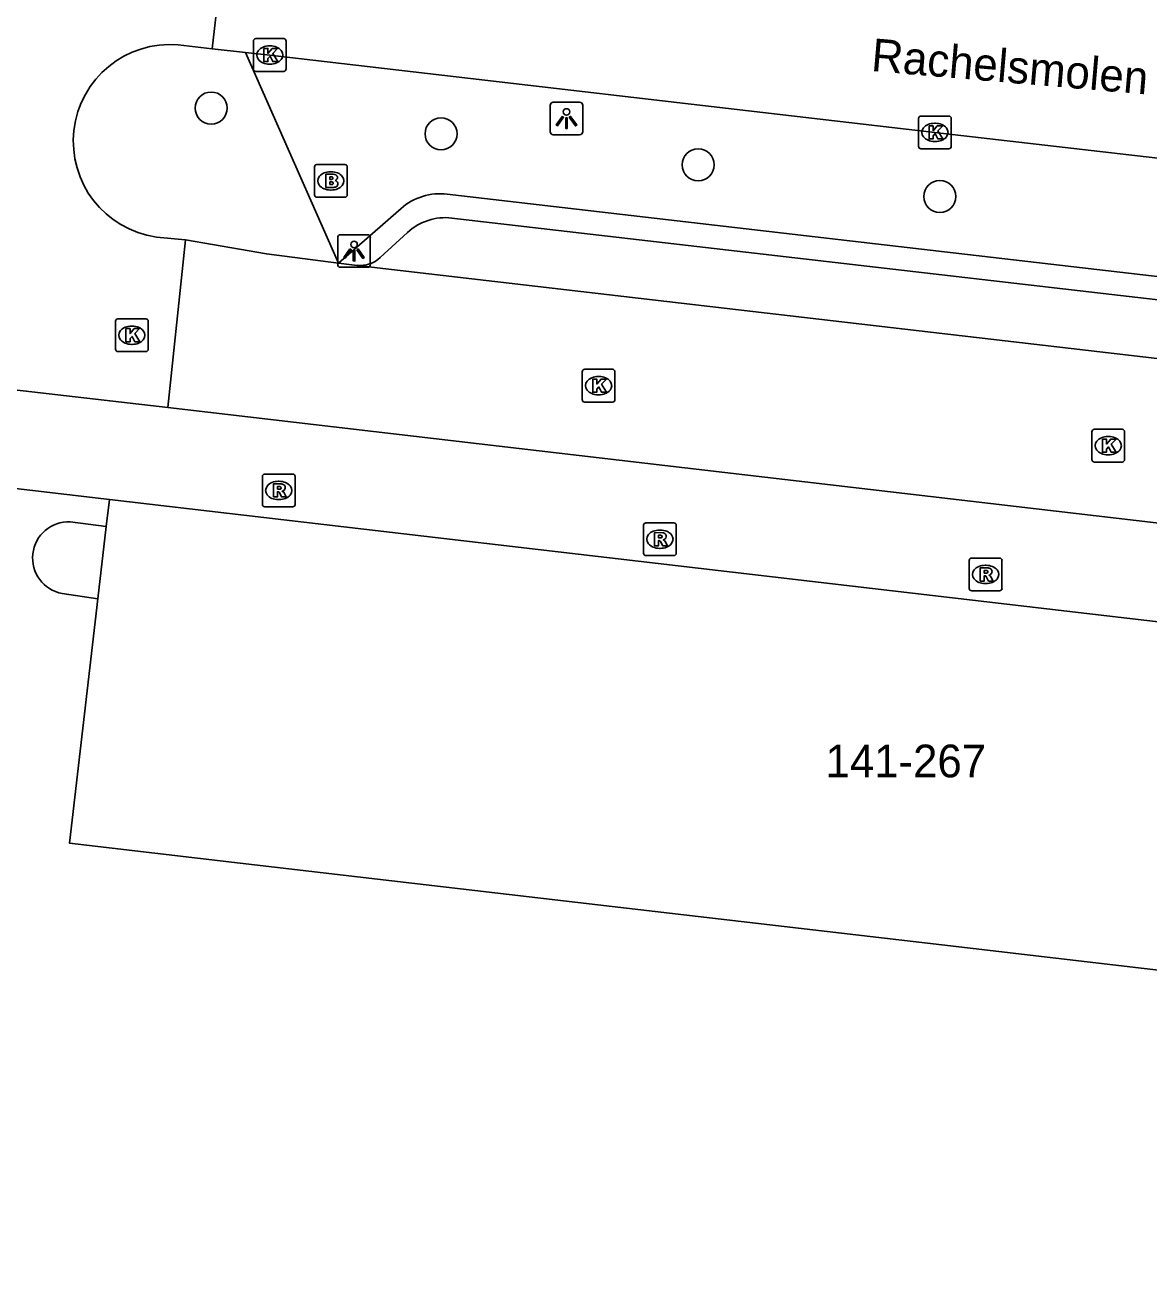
# Model space of a CAD drawing. Extents: x 161243 to 161752, y 384138 to 384885.
# Drawn here: x 161530.14 to 161564.47, y 384599.27 to 384637.78 of the extents above; entities that cross this region are included whole.
import ezdxf

# ---------------------------------------------------------------- set-up
doc = ezdxf.new("R2010")
doc.units = 0
for name, color, linetype in [('IMGEO_Berm_groen', 7, 'Continuous'), ('IMGEO_Boom', 7, 'Continuous'), ('IMGEO_Brandkraan', 7, 'Continuous'), ('IMGEO_Kolk', 7, 'Continuous'), ('IMGEO_Lichtpunt', 7, 'Continuous'), ('IMGEO_Openbare_ruimte_label', 7, 'Continuous'), ('IMGEO_Pand', 7, 'Continuous'), ('IMGEO_Pand_nummerreeks', 7, 'Continuous'), ('IMGEO_Rijbaan_lokaal_open', 7, 'Continuous'), ('IMGEO_Rioolput', 7, 'Continuous'), ('IMGEO_Voetpad_open', 7, 'Continuous')]:
    doc.layers.add(name, color=color, linetype=linetype)

msp = doc.modelspace()

# ---------------------------------------------------------------- linework, layer by layer
at = {"layer": 'IMGEO_Berm_groen'}
msp.add_lwpolyline([(161539.715, 384630.511), (161536.877, 384636.946)], dxfattribs=at)
at = {"layer": 'IMGEO_Boom'}
for centre in [(161535.824, 384635.246), (161542.847, 384634.458), (161550.703, 384633.512), (161558.087, 384632.544)]:
    msp.add_circle(centre, 0.489, dxfattribs=at)
at = {"layer": 'IMGEO_Brandkraan'}
for p, q in [((161538.979, 384632.596), (161538.979, 384633.448)), ((161539.054, 384633.522), (161539.906, 384633.522)), ((161539.467, 384633.302), (161539.492, 384633.302)), ((161539.98, 384633.448), (161539.98, 384632.596)), ((161539.906, 384632.522), (161539.054, 384632.522)), ((161539.49, 384632.742), (161539.465, 384632.742))]:
    msp.add_line(p, q, dxfattribs=at)
for points in [[(161538.979, 384632.596), (161538.979, 384633.448)], [(161539.054, 384633.522), (161539.906, 384633.522)], [(161539.98, 384633.448), (161539.98, 384632.596)], [(161539.327, 384633.222), (161539.327, 384632.822), (161539.54, 384632.822)], [(161539.558, 384633.222), (161539.327, 384633.222)], [(161539.506, 384633.141), (161539.452, 384633.141), (161539.452, 384633.065)], [(161539.452, 384633.065), (161539.505, 384633.065)], [(161539.514, 384632.989), (161539.452, 384632.989), (161539.452, 384632.908)], [(161539.452, 384632.908), (161539.514, 384632.908)], [(161539.906, 384632.522), (161539.054, 384632.522)]]:
    msp.add_lwpolyline(points, dxfattribs=at)
for centre, radius, start, end in [((161539.056, 384633.446), 0.0765, 91.552, 178.448), ((161539.056, 384633.446), 0.0765, 91.552, 178.448), ((161539.904, 384633.446), 0.0765, 1.552, 88.448), ((161539.904, 384633.446), 0.0765, 1.552, 88.448), ((161539.507, 384633.103), 0.0379, 267.8285, 90.9355), ((161539.515, 384632.948), 0.0404, 269.8759, 90.5077), ((161539.546, 384633.073), 0.251, 268.6676, 293.5347), ((161539.562, 384633.077), 0.145, 59.4692, 91.5367), ((161539.587, 384633.124), 0.0922, 285.5137, 58.1501), ((161539.592, 384632.932), 0.105, 301.3115, 78.989), ((161539.056, 384632.598), 0.0765, 181.552, 268.448), ((161539.056, 384632.598), 0.0765, 181.552, 268.448), ((161539.904, 384632.598), 0.0765, 271.552, 358.448), ((161539.904, 384632.598), 0.0765, 271.552, 358.448)]:
    msp.add_arc(centre, radius, start, end, dxfattribs=at)
for centre, major_axis, ratio, start_param, end_param in [((161539.466, 384633.022), (-0.387, 0.002), 0.722429, 4.712389, 7.853982), ((161539.491, 384633.022), (-0.39, 0.002), 0.717154, 1.570796, 4.712389)]:
    msp.add_ellipse(centre, major_axis=major_axis, ratio=ratio, start_param=start_param, end_param=end_param, dxfattribs=at)
at = {"layer": 'IMGEO_Kolk'}
for p, q in [((161537.114, 384636.441), (161537.114, 384637.293)), ((161537.189, 384637.367), (161538.041, 384637.367)), ((161537.602, 384637.147), (161537.627, 384637.147)), ((161538.115, 384637.293), (161538.115, 384636.441)), ((161538.041, 384636.367), (161537.189, 384636.367)), ((161537.625, 384636.587), (161537.6, 384636.587)), ((161557.438, 384634.076), (161557.438, 384634.928)), ((161557.513, 384635.002), (161558.365, 384635.002)), ((161557.926, 384634.782), (161557.951, 384634.782)), ((161558.439, 384634.928), (161558.439, 384634.076)), ((161558.365, 384634.002), (161557.513, 384634.002)), ((161557.949, 384634.222), (161557.924, 384634.222)), ((161532.899, 384627.882), (161532.899, 384628.734)), ((161532.974, 384628.808), (161533.826, 384628.808)), ((161533.9, 384628.734), (161533.9, 384627.882)), ((161533.387, 384628.588), (161533.412, 384628.588)), ((161533.41, 384628.028), (161533.385, 384628.028)), ((161533.826, 384627.808), (161532.974, 384627.808)), ((161547.161, 384626.34), (161547.161, 384627.192)), ((161547.236, 384627.266), (161548.088, 384627.266)), ((161548.162, 384627.192), (161548.162, 384626.34)), ((161547.649, 384627.046), (161547.674, 384627.046)), ((161547.672, 384626.486), (161547.647, 384626.486)), ((161548.088, 384626.266), (161547.236, 384626.266)), ((161562.735, 384624.508), (161562.735, 384625.36)), ((161562.81, 384625.434), (161563.662, 384625.434)), ((161563.223, 384625.214), (161563.248, 384625.214)), ((161563.736, 384625.36), (161563.736, 384624.508)), ((161563.662, 384624.434), (161562.81, 384624.434)), ((161563.246, 384624.654), (161563.221, 384624.654))]:
    msp.add_line(p, q, dxfattribs=at)
for points in [[(161537.114, 384636.441), (161537.114, 384637.293)], [(161537.189, 384637.367), (161538.041, 384637.367)], [(161538.115, 384637.293), (161538.115, 384636.441)], [(161537.435, 384637.067), (161537.558, 384637.067), (161537.558, 384636.916), (161537.688, 384637.067), (161537.852, 384637.067), (161537.706, 384636.916), (161537.859, 384636.667), (161537.707, 384636.667), (161537.622, 384636.831), (161537.558, 384636.764), (161537.558, 384636.667), (161537.435, 384636.667), (161537.435, 384637.067)], [(161538.041, 384636.367), (161537.189, 384636.367)], [(161557.438, 384634.076), (161557.438, 384634.928)], [(161557.513, 384635.002), (161558.365, 384635.002)], [(161558.439, 384634.928), (161558.439, 384634.076)], [(161557.759, 384634.702), (161557.882, 384634.702), (161557.882, 384634.551), (161558.012, 384634.702), (161558.176, 384634.702), (161558.03, 384634.551), (161558.183, 384634.302), (161558.031, 384634.302), (161557.946, 384634.466), (161557.882, 384634.399), (161557.882, 384634.302), (161557.759, 384634.302), (161557.759, 384634.702)], [(161558.365, 384634.002), (161557.513, 384634.002)], [(161532.899, 384627.882), (161532.899, 384628.734)], [(161532.974, 384628.808), (161533.826, 384628.808)], [(161533.9, 384628.734), (161533.9, 384627.882)], [(161533.22, 384628.508), (161533.343, 384628.508), (161533.343, 384628.357), (161533.473, 384628.508), (161533.637, 384628.508), (161533.491, 384628.357), (161533.644, 384628.108), (161533.492, 384628.108), (161533.407, 384628.272), (161533.343, 384628.205), (161533.343, 384628.108), (161533.22, 384628.108), (161533.22, 384628.508)], [(161533.826, 384627.808), (161532.974, 384627.808)], [(161547.161, 384626.34), (161547.161, 384627.192)], [(161547.236, 384627.266), (161548.088, 384627.266)], [(161548.162, 384627.192), (161548.162, 384626.34)], [(161547.482, 384626.966), (161547.605, 384626.966), (161547.605, 384626.815), (161547.735, 384626.966), (161547.899, 384626.966), (161547.753, 384626.815), (161547.906, 384626.566), (161547.754, 384626.566), (161547.669, 384626.73), (161547.605, 384626.663), (161547.605, 384626.566), (161547.482, 384626.566), (161547.482, 384626.966)], [(161548.088, 384626.266), (161547.236, 384626.266)], [(161562.735, 384624.508), (161562.735, 384625.36)], [(161562.81, 384625.434), (161563.662, 384625.434)], [(161563.736, 384625.36), (161563.736, 384624.508)], [(161563.056, 384625.134), (161563.179, 384625.134), (161563.179, 384624.983), (161563.309, 384625.134), (161563.473, 384625.134), (161563.327, 384624.983), (161563.48, 384624.734), (161563.328, 384624.734), (161563.243, 384624.898), (161563.179, 384624.831), (161563.179, 384624.734), (161563.056, 384624.734), (161563.056, 384625.134)], [(161563.662, 384624.434), (161562.81, 384624.434)]]:
    msp.add_lwpolyline(points, dxfattribs=at)
for centre, start, end in [((161537.191, 384637.291), 91.552, 178.448), ((161537.191, 384637.291), 91.552, 178.448), ((161538.039, 384637.291), 1.552, 88.448), ((161538.039, 384637.291), 1.552, 88.448), ((161537.191, 384636.443), 181.552, 268.448), ((161537.191, 384636.443), 181.552, 268.448), ((161538.039, 384636.443), 271.552, 358.448), ((161538.039, 384636.443), 271.552, 358.448), ((161557.515, 384634.926), 91.552, 178.448), ((161557.515, 384634.926), 91.552, 178.448), ((161558.363, 384634.926), 1.552, 88.448), ((161558.363, 384634.926), 1.552, 88.448), ((161557.515, 384634.078), 181.552, 268.448), ((161557.515, 384634.078), 181.552, 268.448), ((161558.363, 384634.078), 271.552, 358.448), ((161558.363, 384634.078), 271.552, 358.448), ((161532.976, 384628.732), 91.552, 178.448), ((161532.976, 384628.732), 91.552, 178.448), ((161533.824, 384628.732), 1.552, 88.448), ((161533.824, 384628.732), 1.552, 88.448), ((161532.976, 384627.884), 181.552, 268.448), ((161532.976, 384627.884), 181.552, 268.448), ((161533.824, 384627.884), 271.552, 358.448), ((161533.824, 384627.884), 271.552, 358.448), ((161547.238, 384627.19), 91.552, 178.448), ((161547.238, 384627.19), 91.552, 178.448), ((161548.086, 384627.19), 1.552, 88.448), ((161548.086, 384627.19), 1.552, 88.448), ((161547.238, 384626.342), 181.552, 268.448), ((161547.238, 384626.342), 181.552, 268.448), ((161548.086, 384626.342), 271.552, 358.448), ((161548.086, 384626.342), 271.552, 358.448), ((161562.812, 384625.358), 91.552, 178.448), ((161562.812, 384625.358), 91.552, 178.448), ((161563.66, 384625.358), 1.552, 88.448), ((161563.66, 384625.358), 1.552, 88.448), ((161562.812, 384624.51), 181.552, 268.448), ((161562.812, 384624.51), 181.552, 268.448), ((161563.66, 384624.51), 271.552, 358.448), ((161563.66, 384624.51), 271.552, 358.448)]:
    msp.add_arc(centre, 0.0765, start, end, dxfattribs=at)
for centre, major_axis, ratio, start_param, end_param in [((161537.601, 384636.867), (-0.387, 0.002), 0.722429, 4.712389, 7.853982), ((161537.626, 384636.867), (-0.39, 0.002), 0.717154, 1.570796, 4.712389), ((161557.925, 384634.502), (-0.387, 0.002), 0.722429, 4.712389, 7.853982), ((161557.95, 384634.502), (-0.39, 0.002), 0.717154, 1.570796, 4.712389), ((161533.386, 384628.308), (-0.387, 0.002), 0.722429, 4.712389, 7.853982), ((161533.411, 384628.308), (-0.39, 0.002), 0.717154, 1.570796, 4.712389), ((161547.648, 384626.766), (-0.387, 0.002), 0.722429, 4.712389, 7.853982), ((161547.673, 384626.766), (-0.39, 0.002), 0.717154, 1.570796, 4.712389), ((161563.222, 384624.934), (-0.387, 0.002), 0.722429, 4.712389, 7.853982), ((161563.247, 384624.934), (-0.39, 0.002), 0.717154, 1.570796, 4.712389)]:
    msp.add_ellipse(centre, major_axis=major_axis, ratio=ratio, start_param=start_param, end_param=end_param, dxfattribs=at)
at = {"layer": 'IMGEO_Lichtpunt'}
for p, q in [((161546.181, 384635.33), (161546.181, 384634.523)), ((161546.181, 384635.33), (161546.181, 384634.523)), ((161547.083, 384635.425), (161546.275, 384635.425)), ((161547.083, 384635.425), (161546.275, 384635.425)), ((161547.177, 384634.523), (161547.177, 384635.33)), ((161547.177, 384634.523), (161547.177, 384635.33)), ((161546.275, 384634.429), (161547.083, 384634.429)), ((161546.275, 384634.429), (161547.083, 384634.429)), ((161540.592, 384631.378), (161539.784, 384631.378)), ((161540.592, 384631.378), (161539.784, 384631.378)), ((161539.69, 384631.283), (161539.69, 384630.476)), ((161539.69, 384631.283), (161539.69, 384630.476)), ((161540.686, 384630.476), (161540.686, 384631.283)), ((161540.686, 384630.476), (161540.686, 384631.283)), ((161539.784, 384630.382), (161540.592, 384630.382)), ((161539.784, 384630.382), (161540.592, 384630.382))]:
    msp.add_line(p, q, dxfattribs=at)
for points in [[(161546.555, 384634.994), (161546.594, 384634.966), (161546.406, 384634.704), (161546.368, 384634.731), (161546.555, 384634.994)], [(161546.657, 384634.946), (161546.704, 384634.946), (161546.704, 384634.624), (161546.657, 384634.624), (161546.657, 384634.946)], [(161546.767, 384634.966), (161546.805, 384634.993), (161546.992, 384634.731), (161546.953, 384634.703), (161546.767, 384634.966)], [(161540.064, 384630.947), (161540.103, 384630.919), (161539.915, 384630.657), (161539.877, 384630.684), (161540.064, 384630.947)], [(161540.276, 384630.919), (161540.314, 384630.946), (161540.501, 384630.684), (161540.462, 384630.656), (161540.276, 384630.919)], [(161540.166, 384630.899), (161540.213, 384630.899), (161540.213, 384630.577), (161540.166, 384630.577), (161540.166, 384630.899)]]:
    msp.add_lwpolyline(points, dxfattribs=at)
for centre in [(161546.68, 384635.128), (161540.189, 384631.081)]:
    msp.add_circle(centre, 0.0994, dxfattribs=at)
for centre, start, end in [((161546.275, 384635.33), 90, 180), ((161546.275, 384635.33), 90, 180), ((161547.083, 384635.33), 0, 90), ((161547.083, 384635.33), 0, 90), ((161546.275, 384634.523), 180, 270), ((161546.275, 384634.523), 180, 270), ((161547.083, 384634.523), 270, 0), ((161547.083, 384634.523), 270, 360), ((161539.784, 384631.283), 90, 180), ((161539.784, 384631.283), 90, 180), ((161540.592, 384631.283), 0, 90), ((161540.592, 384631.283), 0, 90), ((161539.784, 384630.476), 180, 270), ((161539.784, 384630.476), 180, 270), ((161540.592, 384630.476), 270, 0), ((161540.592, 384630.476), 270, 360)]:
    msp.add_arc(centre, 0.0946, start, end, dxfattribs=at)
at = {"layer": 'IMGEO_Pand'}
for points in [[(161532.618, 384622.461), (161532.715, 384623.292)], [(161532.715, 384623.292), (161578.119, 384617.994), (161577.7, 384614.463)], [(161532.361, 384620.26), (161532.618, 384622.461)], [(161570.138, 384540.132), (161570.443, 384542.795), (161568.946, 384542.971), (161569.566, 384548.298), (161570.885, 384559.629), (161572.061, 384569.733), (161573.384, 384581.093), (161574.574, 384591.319), (161575.896, 384602.674), (161576.464, 384607.551), (161569.557, 384608.356), (161558.148, 384609.686), (161548.08, 384610.859), (161536.711, 384612.184), (161531.489, 384612.793), (161532.361, 384620.26)]]:
    msp.add_lwpolyline(points, dxfattribs=at)
at = {"layer": 'IMGEO_Rijbaan_lokaal_open'}
for points in [[(161535.856, 384637.056), (161536.578, 384643.359)], [(161534.817, 384637.177), (161535.856, 384637.056)], [(161536.877, 384636.946), (161535.856, 384637.056)], [(161579.486, 384631.977), (161578.288, 384632.155), (161557.939, 384634.502), (161537.615, 384636.867), (161536.877, 384636.946)], [(161535.036, 384631.221), (161534.151, 384631.305)], [(161535.036, 384631.221), (161534.497, 384626.098)], [(161539.715, 384630.511), (161537.509, 384630.792), (161535.036, 384631.221)], [(161540.282, 384630.442), (161539.715, 384630.511)], [(161599.071, 384623.606), (161540.282, 384630.442)], [(161534.497, 384626.098), (161529.178, 384626.708), (161529.056, 384625.677)], [(161534.497, 384626.098), (161579.881, 384620.805)]]:
    msp.add_lwpolyline(points, dxfattribs=at)
msp.add_arc((161534.567, 384634.232), 2.956, 85.1388, 261.9196, dxfattribs=at)
at = {"layer": 'IMGEO_Rioolput'}
for p, q in [((161537.387, 384623.14), (161537.387, 384623.992)), ((161537.462, 384624.066), (161538.314, 384624.066)), ((161538.388, 384623.992), (161538.388, 384623.14)), ((161537.875, 384623.846), (161537.9, 384623.846)), ((161537.898, 384623.286), (161537.873, 384623.286)), ((161538.314, 384623.066), (161537.462, 384623.066)), ((161549.034, 384621.651), (161549.034, 384622.503)), ((161549.109, 384622.577), (161549.961, 384622.577)), ((161550.035, 384622.503), (161550.035, 384621.651)), ((161549.522, 384622.357), (161549.547, 384622.357)), ((161549.545, 384621.797), (161549.52, 384621.797)), ((161549.961, 384621.577), (161549.109, 384621.577)), ((161558.987, 384620.574), (161558.987, 384621.426)), ((161559.062, 384621.5), (161559.914, 384621.5)), ((161559.988, 384621.426), (161559.988, 384620.574)), ((161559.475, 384621.28), (161559.5, 384621.28)), ((161559.498, 384620.72), (161559.473, 384620.72)), ((161559.914, 384620.5), (161559.062, 384620.5))]:
    msp.add_line(p, q, dxfattribs=at)
for points in [[(161537.387, 384623.14), (161537.387, 384623.992)], [(161537.462, 384624.066), (161538.314, 384624.066)], [(161538.388, 384623.992), (161538.388, 384623.14)], [(161537.976, 384623.764), (161537.724, 384623.766), (161537.724, 384623.366)], [(161537.902, 384623.685), (161537.848, 384623.685), (161537.848, 384623.604)], [(161537.848, 384623.604), (161537.9, 384623.604)], [(161537.724, 384623.366), (161537.848, 384623.366), (161537.848, 384623.528), (161537.859, 384623.528)], [(161537.906, 384623.499), (161537.977, 384623.366), (161538.117, 384623.366), (161538.052, 384623.492)], [(161538.314, 384623.066), (161537.462, 384623.066)], [(161549.034, 384621.651), (161549.034, 384622.503)], [(161549.109, 384622.577), (161549.961, 384622.577)], [(161550.035, 384622.503), (161550.035, 384621.651)], [(161549.623, 384622.275), (161549.371, 384622.277), (161549.371, 384621.877)], [(161549.549, 384622.196), (161549.495, 384622.196), (161549.495, 384622.115)], [(161549.495, 384622.115), (161549.547, 384622.115)], [(161549.371, 384621.877), (161549.495, 384621.877), (161549.495, 384622.039), (161549.506, 384622.039)], [(161549.553, 384622.01), (161549.624, 384621.877), (161549.764, 384621.877), (161549.699, 384622.003)], [(161549.961, 384621.577), (161549.109, 384621.577)], [(161558.987, 384620.574), (161558.987, 384621.426)], [(161559.062, 384621.5), (161559.914, 384621.5)], [(161559.988, 384621.426), (161559.988, 384620.574)], [(161559.576, 384621.198), (161559.324, 384621.2), (161559.324, 384620.8)], [(161559.324, 384620.8), (161559.448, 384620.8), (161559.448, 384620.962), (161559.459, 384620.962)], [(161559.502, 384621.119), (161559.448, 384621.119), (161559.448, 384621.038)], [(161559.448, 384621.038), (161559.5, 384621.038)], [(161559.506, 384620.933), (161559.577, 384620.8), (161559.717, 384620.8), (161559.652, 384620.926)], [(161559.914, 384620.5), (161559.062, 384620.5)]]:
    msp.add_lwpolyline(points, dxfattribs=at)
for centre, radius, start, end in [((161537.464, 384623.99), 0.0765, 91.552, 178.448), ((161537.464, 384623.99), 0.0765, 91.552, 178.448), ((161538.312, 384623.99), 0.0765, 1.552, 88.448), ((161538.312, 384623.99), 0.0765, 1.552, 88.448), ((161537.884, 384623.793), 0.19, 274.7715, 282.9687), ((161537.908, 384623.589), 0.0964, 77.0061, 93.1865), ((161537.922, 384623.646), 0.0378, 276.6634, 79.6772), ((161537.975, 384623.654), 0.109, 350.3612, 89.416), ((161537.973, 384623.654), 0.112, 277.5842, 350.9817), ((161537.858, 384623.475), 0.0533, 26.0293, 88.6989), ((161537.957, 384623.439), 0.108, 29.5134, 73.7905), ((161537.464, 384623.142), 0.0765, 181.552, 268.448), ((161537.464, 384623.142), 0.0765, 181.552, 268.448), ((161538.312, 384623.142), 0.0765, 271.552, 358.448), ((161538.312, 384623.142), 0.0765, 271.552, 358.448), ((161549.111, 384622.501), 0.0765, 91.552, 178.448), ((161549.111, 384622.501), 0.0765, 91.552, 178.448), ((161549.959, 384622.501), 0.0765, 1.552, 88.448), ((161549.959, 384622.501), 0.0765, 1.552, 88.448), ((161549.531, 384622.304), 0.19, 274.7715, 282.9687), ((161549.555, 384622.1), 0.0964, 77.0061, 93.1865), ((161549.569, 384622.157), 0.0378, 276.6634, 79.6772), ((161549.622, 384622.165), 0.109, 350.3612, 89.416), ((161549.62, 384622.165), 0.112, 277.5842, 350.9817), ((161549.505, 384621.986), 0.0533, 26.0293, 88.6989), ((161549.604, 384621.95), 0.108, 29.5134, 73.7905), ((161549.111, 384621.653), 0.0765, 181.552, 268.448), ((161549.111, 384621.653), 0.0765, 181.552, 268.448), ((161549.959, 384621.653), 0.0765, 271.552, 358.448), ((161549.959, 384621.653), 0.0765, 271.552, 358.448), ((161559.064, 384621.424), 0.0765, 91.552, 178.448), ((161559.064, 384621.424), 0.0765, 91.552, 178.448), ((161559.912, 384621.424), 0.0765, 1.552, 88.448), ((161559.912, 384621.424), 0.0765, 1.552, 88.448), ((161559.458, 384620.909), 0.0533, 26.0293, 88.6989), ((161559.484, 384621.227), 0.19, 274.7715, 282.9687), ((161559.508, 384621.023), 0.0964, 77.0061, 93.1865), ((161559.522, 384621.08), 0.0378, 276.6634, 79.6772), ((161559.575, 384621.088), 0.109, 350.3612, 89.416), ((161559.573, 384621.088), 0.112, 277.5842, 350.9817), ((161559.557, 384620.873), 0.108, 29.5134, 73.7905), ((161559.064, 384620.576), 0.0765, 181.552, 268.448), ((161559.064, 384620.576), 0.0765, 181.552, 268.448), ((161559.912, 384620.576), 0.0765, 271.552, 358.448), ((161559.912, 384620.576), 0.0765, 271.552, 358.448)]:
    msp.add_arc(centre, radius, start, end, dxfattribs=at)
for centre, major_axis, ratio, start_param, end_param in [((161537.874, 384623.566), (-0.387, 0.002), 0.722429, 4.712389, 7.853982), ((161537.899, 384623.566), (-0.39, 0.002), 0.717154, 1.570796, 4.712389), ((161549.521, 384622.077), (-0.387, 0.002), 0.722429, 4.712389, 7.853982), ((161549.546, 384622.077), (-0.39, 0.002), 0.717154, 1.570796, 4.712389), ((161559.474, 384621), (-0.387, 0.002), 0.722429, 4.712389, 7.853982), ((161559.499, 384621), (-0.39, 0.002), 0.717154, 1.570796, 4.712389)]:
    msp.add_ellipse(centre, major_axis=major_axis, ratio=ratio, start_param=start_param, end_param=end_param, dxfattribs=at)
at = {"layer": 'IMGEO_Voetpad_open'}
for points in [[(161592.061, 384626.232), (161592.142, 384626.926), (161543.037, 384632.619)], [(161541.624, 384632.18), (161539.715, 384630.511)], [(161543.182, 384631.888), (161592.061, 384626.232)], [(161540.987, 384630.677), (161541.822, 384631.449)], [(161532.715, 384623.292), (161528.97, 384623.728)], [(161531.518, 384622.608), (161532.618, 384622.461)], [(161532.361, 384620.26), (161531.269, 384620.417)]]:
    msp.add_lwpolyline(points, dxfattribs=at)
for centre, radius, start, end in [((161542.826, 384630.805), 1.826, 83.3612, 131.1574), ((161542.984, 384630.176), 1.723, 83.3944, 132.3851), ((161540.373, 384631.344), 0.906, 264.2254, 312.6445), ((161531.472, 384621.504), 1.105, 87.6346, 259.3981)]:
    msp.add_arc(centre, radius, start, end, dxfattribs=at)

# ---------------------------------------------------------------- texts
at = {"layer": 'IMGEO_Openbare_ruimte_label'}
msp.add_text('Rachelsmolen', height=1, rotation=355.1221, dxfattribs=at).set_placement((161555.97, 384636.382))
at = {"layer": 'IMGEO_Pand_nummerreeks'}
msp.add_text('141-267', height=1, rotation=360, dxfattribs=at).set_placement((161554.595, 384614.802))

doc.saveas('drawing.dxf')
